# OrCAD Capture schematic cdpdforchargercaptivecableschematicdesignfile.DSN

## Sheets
1 2 History_Sheet: title: Revision History; rev: 1.6
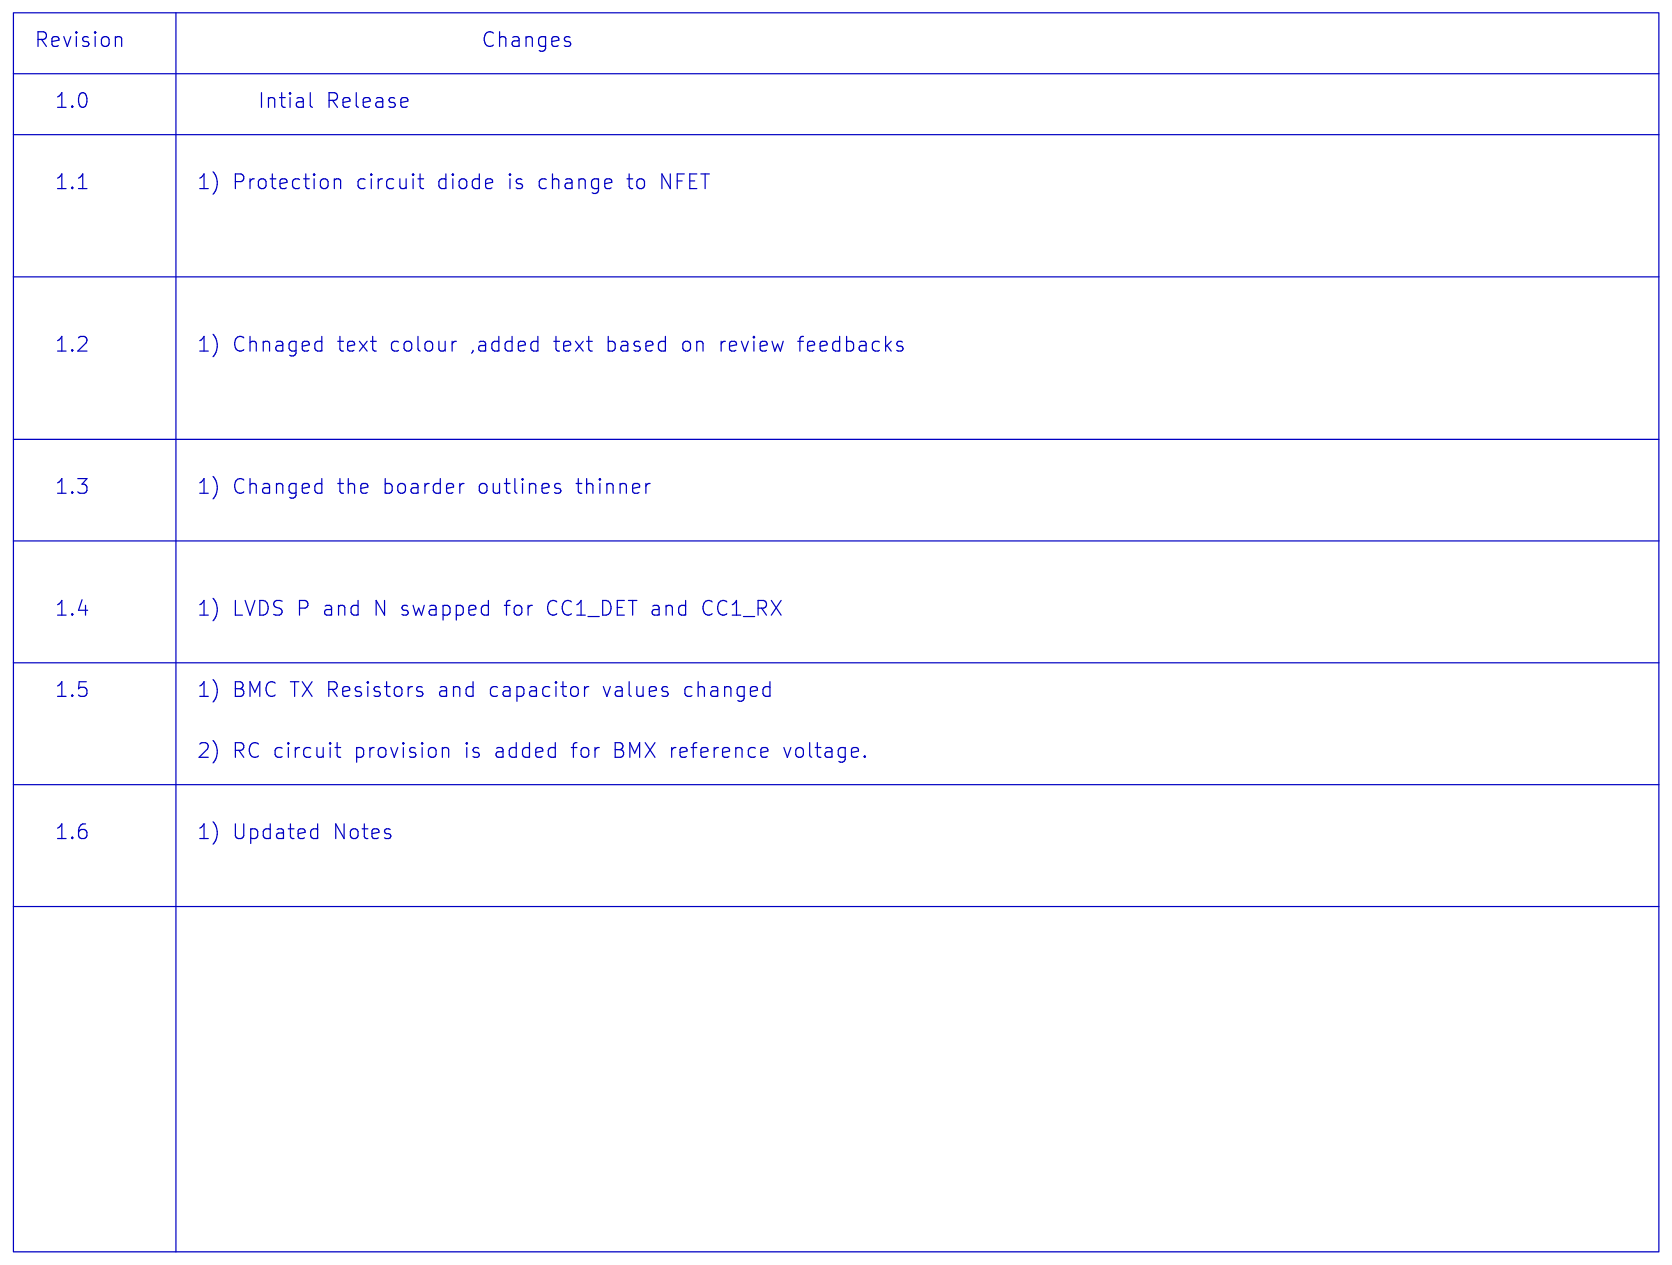
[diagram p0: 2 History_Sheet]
2 1 CD_PD_Charger_Captive: size B; title: CD_PD_Charger_Captive
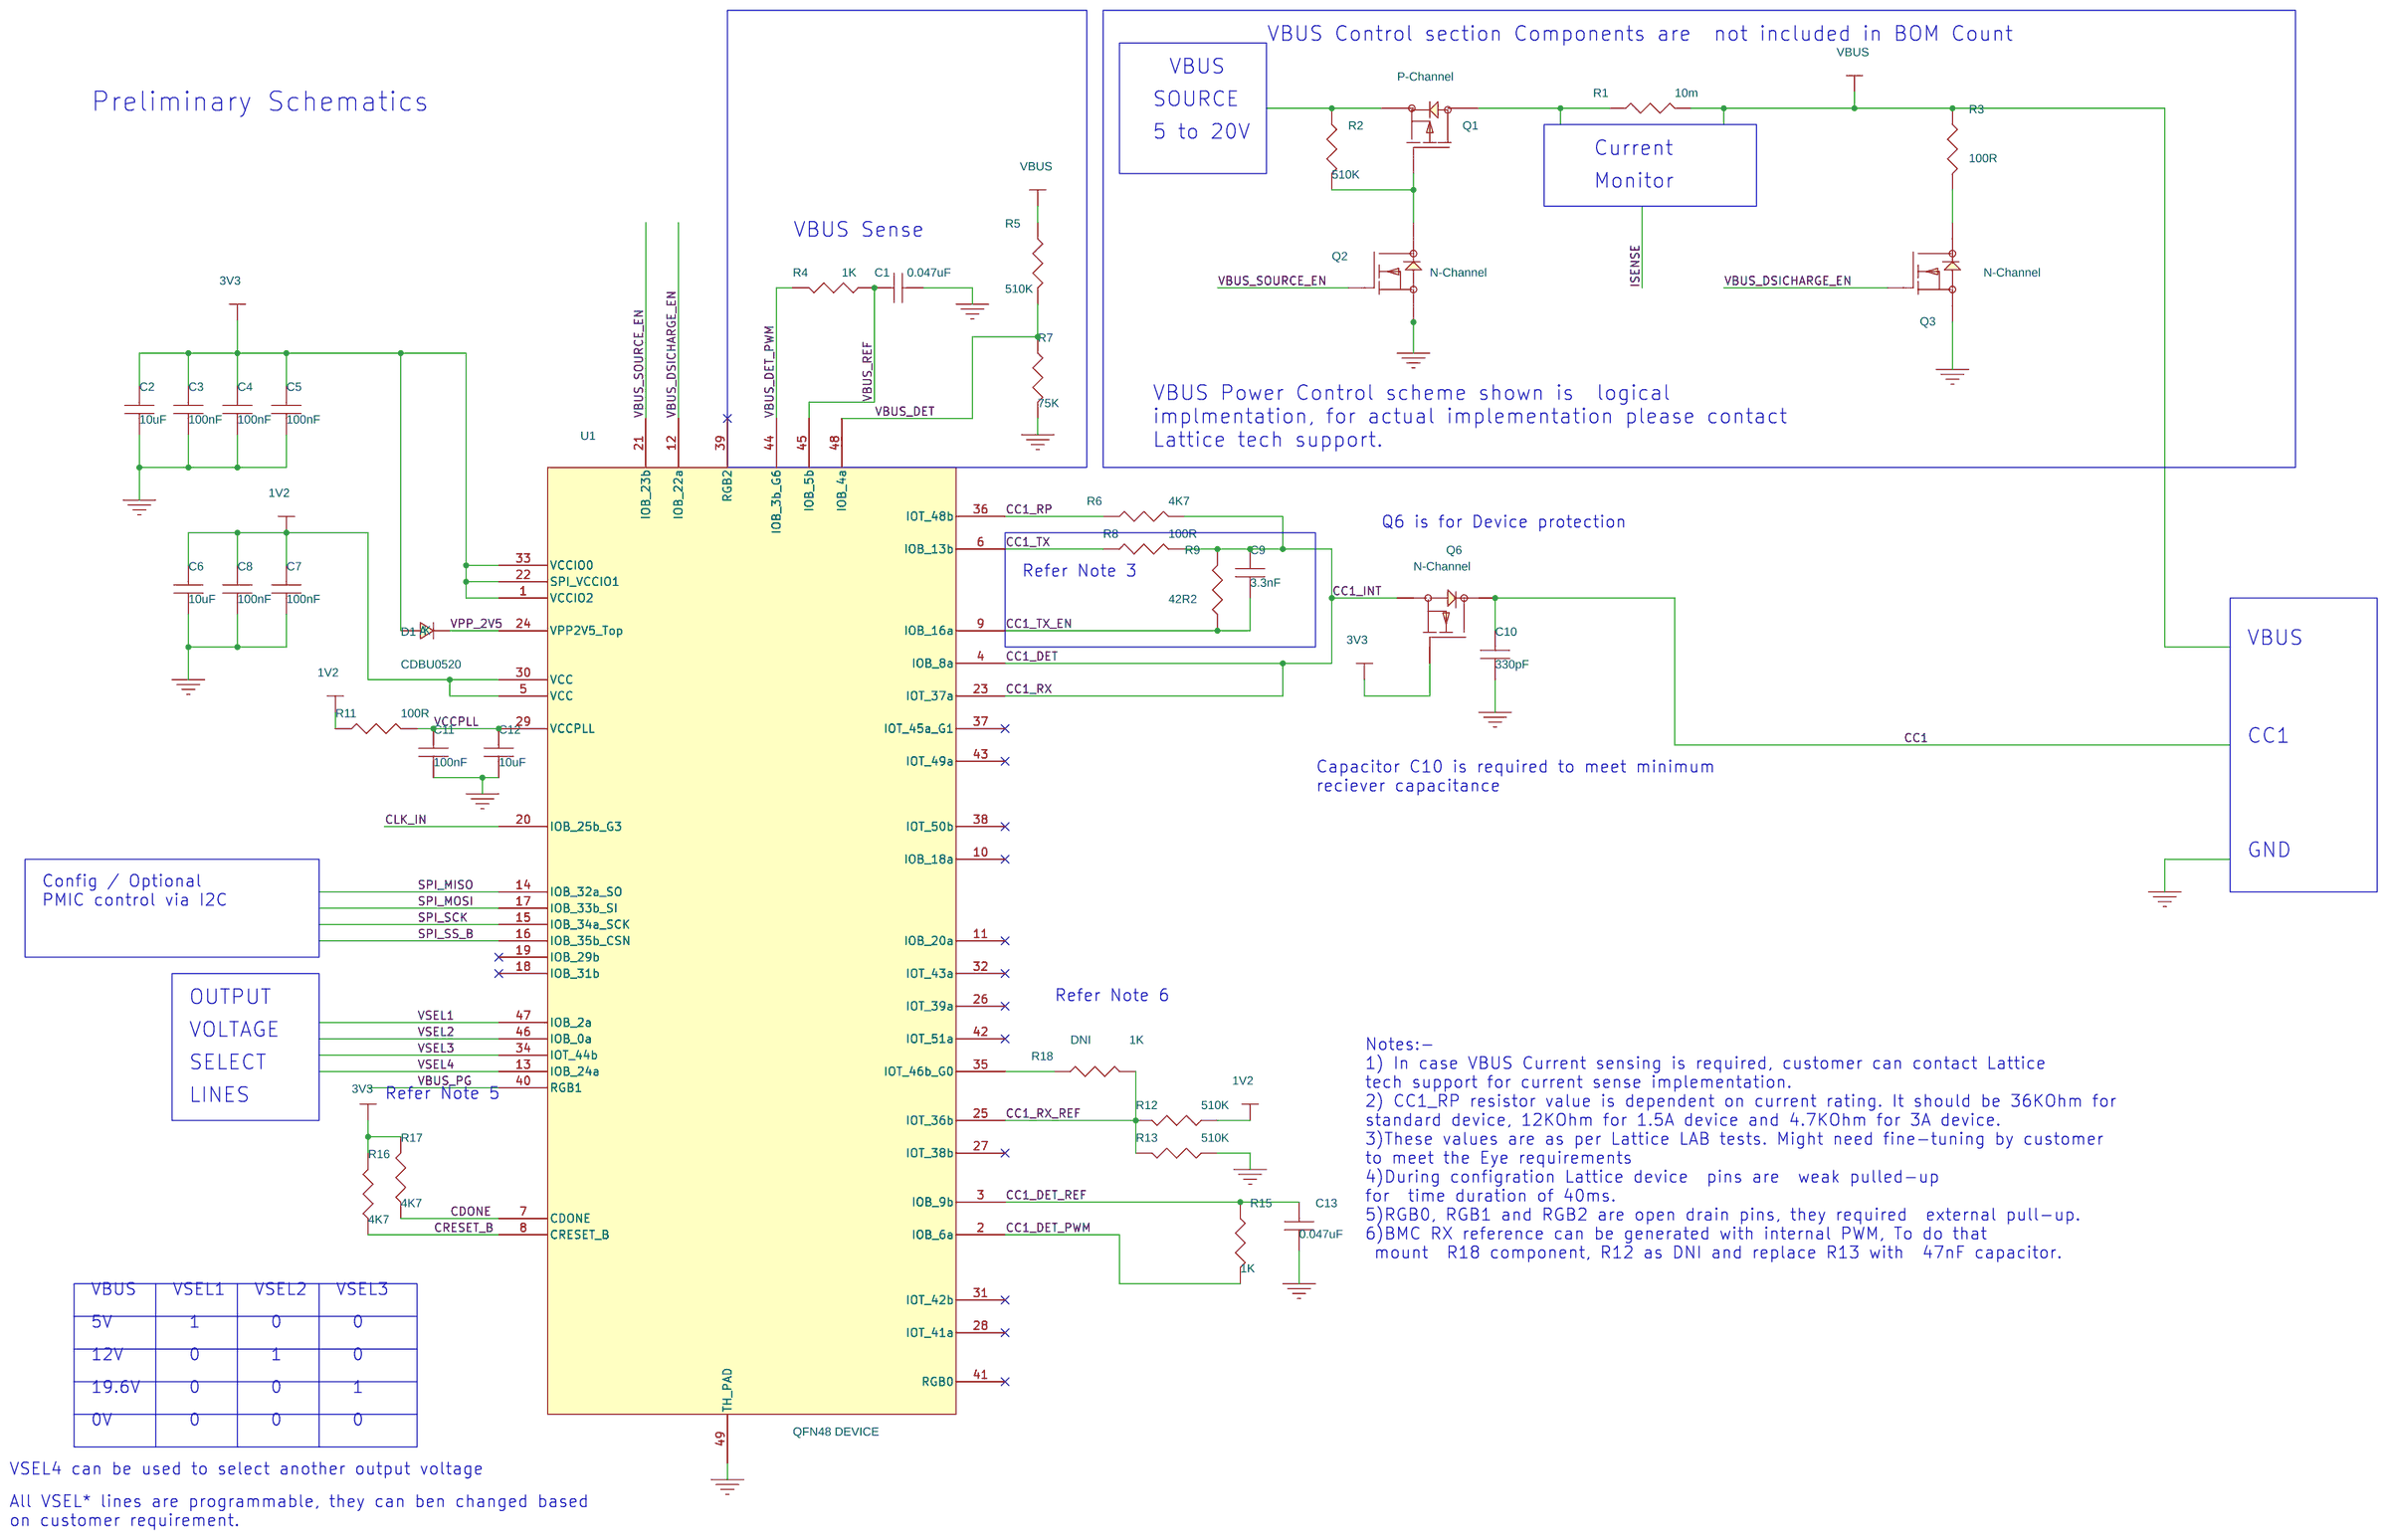
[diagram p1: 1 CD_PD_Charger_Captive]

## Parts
C1  0.047uF  [C0402]
C2  10uF  [C0805]
C3  100nF  [C0402]
C4  100nF  [C0402]
C5  100nF  [C0402]
C6  10uF  [C0805]
C7  100nF  [C0402]
C8  100nF  [C0402]
C9  3.3nF  [C0402]
C10  330pF  [C0402]
C11  100nF  [C0402]
C12  10uF  [C0805]
C13  0.047uF  [C0402]
D1  CDBU0520  [D0603]
Q1  P-Channel
Q2  N-Channel
Q3  N-Channel
Q6  N-Channel  [BSH103,235]
R1  10m  [R1206]
R2  510K  [R0402]
R3  100R  [R0402]
R4  1K  [R0402]
R5  510K  [R0402]
R6  4K7  [R0402]
R7  75K  [R0402]
R8  100R  [R0402]
R9  42R2  [R0402]
R11  100R  [R0402]
R12  510K  [R0402]
R13  510K  [R0402]
R15  1K  [R0402]
R16  4K7  [R0402]
R17  4K7  [R0402]
R18  1K  [R0402]
U1  QFN48 DEVICE

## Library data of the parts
C1 C13 = CAP_CER_0.047uF_0402_10V
C2 C6 C12 = CAP_CER_10uF_0805_10V
C3-C5 C7 C8 C11 = CAP_CER_100nF_0402_10V
C9 = CAP_CER_3.3nF_0402_10V
C10 = CAP_CER_330pF_0402_16V
D1 = DIODE_SCHOTTKY_20V_0603
Q1 = MOSFET_P-CHAN-1V_6A
Q2 = MOSFET_N-CHAN-0P45V_0P85A
Q3 = PWR_MOSFET-N-CH-0P9V_6P1A
Q6 = MOSFET_N-CHAN-0P45V_1
R1 = RES_10m_1W2_1206_1P
R2 R5 R12 R13 = RES_500K_1W16_0402_5P
R3 = RES_100R_1W_2512_1P
R4 R15 = RES_1K_1W16_0402_5P
R6 R16 R17 = RES_4K7_1W16_0402_5P
R7 = RES_75K_1W16_0402_5P
R8 = RES_100R_1W16_0402_1P
R9 = RES_42R_1W16_0402_1P
R11 = RES_100R_1W16_0402_5P
R18 = RES_1K_1W16_0402_5P: BOM_Note: DNI
U1 = iCE5LP4K__QFN48_New

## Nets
1V2: C6.1 C7.1 C8.1 R11.1 R12.1 U1.5(VCC) U1.30(VCC)
3V3: C2.1 C3.1 C4.1 C5.1 D1.1(A) Q6.1(G) R16.2 R17.2 U1.1(VCCIO2) U1.22(SPI_VCCIO1) U1.33(VCCIO0)
GND: C1.2 C2.2 C3.2 C4.2 C5.2 C6.2 C7.2 C8.2 C10.2 C11.2 C12.2 C13.2 Q2.2(S) Q3.2(S) R7.2 R13.1 U1.49(TH_PAD)
VBUS: R1.2 R3.1 R5.1
VBUS_DET: R5.2 R7.1 U1.48(IOB_4a)
VBUS_DET_PWM: R4.2 U1.44(IOB_3b_G6)
VBUS_DSICHARGE_EN: Q3.1(G) U1.12(IOB_22a)
VBUS_PG: U1.40(RGB1)
VBUS_REF: C1.1 R4.1 U1.45(IOB_5b)
VBUS_SOURCE_EN: Q2.1(G) U1.21(IOB_23b)
VCCPLL: C11.1 C12.1 R11.2 U1.29(VCCPLL)
CC1: C10.1 Q6.3(D)
CC1_DET: C9.1 Q6.2(S) R6.2 R8.2 R9.2 U1.4(IOB_8a) U1.23(IOT_37a)
CC1_DET_PWM: R15.2 U1.2(IOB_6a)
CC1_DET_REF: C13.1 R15.1 U1.3(IOB_9b)
CC1_RP: R6.1 U1.36(IOT_48b)
CC1_RX_REF: R12.2 R13.2 R18.2 U1.25(IOT_36b)
CC1_TX: R8.1 U1.6(IOB_13b)
CC1_TX_EN: C9.2 R9.1 U1.9(IOB_16a)
CDONE: R17.1 U1.7(CDONE)
CLK_IN: U1.20(IOB_25b_G3)
CRESET_B: R16.1 U1.8(CRESET_B)
SPI_MISO: U1.14(IOB_32a_SO)
SPI_MOSI: U1.17(IOB_33b_SI)
SPI_SCK: U1.15(IOB_34a_SCK)
SPI_SS_B: U1.16(IOB_35b_CSN)
VPP_2V5: D1.2(K) U1.24(VPP2V5_Top)
VSEL1: U1.47(IOB_2a)
VSEL2: U1.46(IOB_0a)
VSEL3: U1.34(IOT_44b)
VSEL4: U1.13(IOB_24a)
N16830420: Q1.2(S) R2.1
N16831330: Q1.1(G) Q2.3(D) R2.2
N16844099: Q1.3(D) R1.1
N16844170: Q3.3(D) R3.2
N16862462: R18.1 U1.35(IOT_46b_G0)

Not connected (* = marked no-connect by the designer): U1 10(IOB_18a)* 11(IOB_20a)* 18(IOB_31b)* 19(IOB_29b)* 26(IOT_39a)* 27(IOT_38b)* 28(IOT_41a)* 31(IOT_42b)* 32(IOT_43a)* 37(IOT_45a_G1)* 38(IOT_50b)* 39(RGB2)* 41(RGB0)* 42(IOT_51a)* 43(IOT_49a)*

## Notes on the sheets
sheet 1
- Revision
- Changes
- 1.0
- Intial Release
- 1.1
- 1) Protection circuit diode is change to NFET
- 1.2
- 1) Chnaged text colour ,added text based on review feedbacks
- 1.3
- 1) Changed the boarder outlines thinner
- 1.4
- 1) LVDS P and N swapped for CC1_DET and CC1_RX
- 1.5
- 1) BMC TX Resistors and capacitor values changed
- 2) RC circuit provision is added for BMX reference voltage.
- 1.6
- 1) Updated Notes
sheet 2
- VBUS Control section Components are  not included in BOM Count
- VBUS
- Preliminary Schematics
- SOURCE
- 5 to 20V
- Current
- Monitor
- VBUS Sense
- VBUS Power Control scheme shown is  logical
  implmentation, for actual implementation please contact
  Lattice tech support.
- Q6 is for Device protection
- Refer Note 3
- VBUS
- CC1
- Capacitor C10 is required to meet minimum
  reciever capacitance
- GND
- Config / Optional
  PMIC control via I2C
- OUTPUT
- Refer Note 6
- VOLTAGE
- Notes:-
  1) In case VBUS Current sensing is required, customer can contact Lattice
  tech support for current sense implementation.
  2) CC1_RP resistor value is dependent on current rating. It should be 36KOhm for
  standard device, 12KOhm for 1.5A device and 4.7KOhm for 3A device.
  3)These values are as per Lattice LAB tests. Might need fine-tuning by customer
  to meet the Eye requirements
  4)During configration Lattice device  pins are  weak pulled-up
  for  time duration of 40ms.
  5)RGB0, RGB1 and RGB2 are open drain pins, they required  external pull-up.
  6)BMC RX reference can be generated with internal PWM, To do that
   mount  R18 component, R12 as DNI and replace R13 with  47nF capacitor.
- SELECT
- LINES
- Refer Note 5
- VBUS
- VSEL1
- VSEL2
- VSEL3
- 5V
- 1
- 0
- 0
- 12V
- 0
- 1
- 0
- 19.6V
- 0
- 0
- 1
- 0V
- 0
- 0
- 0
- VSEL4 can be used to select another output voltage
- All VSEL* lines are programmable, they can ben changed based
  on customer requirement.
